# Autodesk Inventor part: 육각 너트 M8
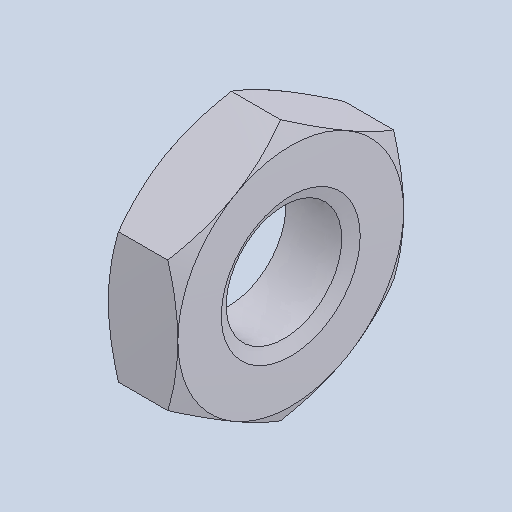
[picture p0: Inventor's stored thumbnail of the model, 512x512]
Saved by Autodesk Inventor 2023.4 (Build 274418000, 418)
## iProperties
Created: 2024-04
Part Number: 육각 너트 M8
Material: 강철, 연강
Description: 6각 너트 및 6각 가는 너트 - 이중 모따기
Document SubType Name: Modeling
Designer: EDU
Density: 7.86 g/cm^3
Appearance: 기본값
Author: jhkim
Sending System: Autodesk Inventor 2025
Preprocessor: ST-DEVELOPER v20
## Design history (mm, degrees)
node "육각 너트 M81"
node "솔리드1"
body "Solid1"
